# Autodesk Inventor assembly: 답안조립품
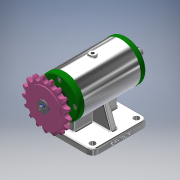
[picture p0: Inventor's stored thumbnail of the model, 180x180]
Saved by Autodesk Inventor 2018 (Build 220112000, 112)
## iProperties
Created: 2019-06
Part Number: 답안조립품
Document SubType Name: Assembly
Designer: Administrator
Author: Administrator
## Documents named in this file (11)
- C:\Users\Administrator\Desktop\490604V1040\답안조립품.iam
- C:\Users\Administrator\Desktop\490604V1040\본체.ipt
- C:\Users\Administrator\Desktop\490604V1040\베어링 6203.ipt
- C:\Users\Administrator\Desktop\490604V1040\축.ipt
- C:\Users\Administrator\Desktop\490604V1040\커버.ipt
- C:\Users\Administrator\Desktop\490604V1040\오일 실 17 30 5.ipt
- C:\Users\Administrator\Desktop\490604V1040\볼트 M4.ipt
- C:\Users\Administrator\Desktop\490604V1040\키 4x4x12.ipt
- C:\Users\Administrator\Desktop\490604V1040\스프로킷.ipt
- C:\Users\Administrator\Desktop\490604V1040\평와셔.ipt
- C:\Users\Administrator\Desktop\490604V1040\스프링와셔.ipt
